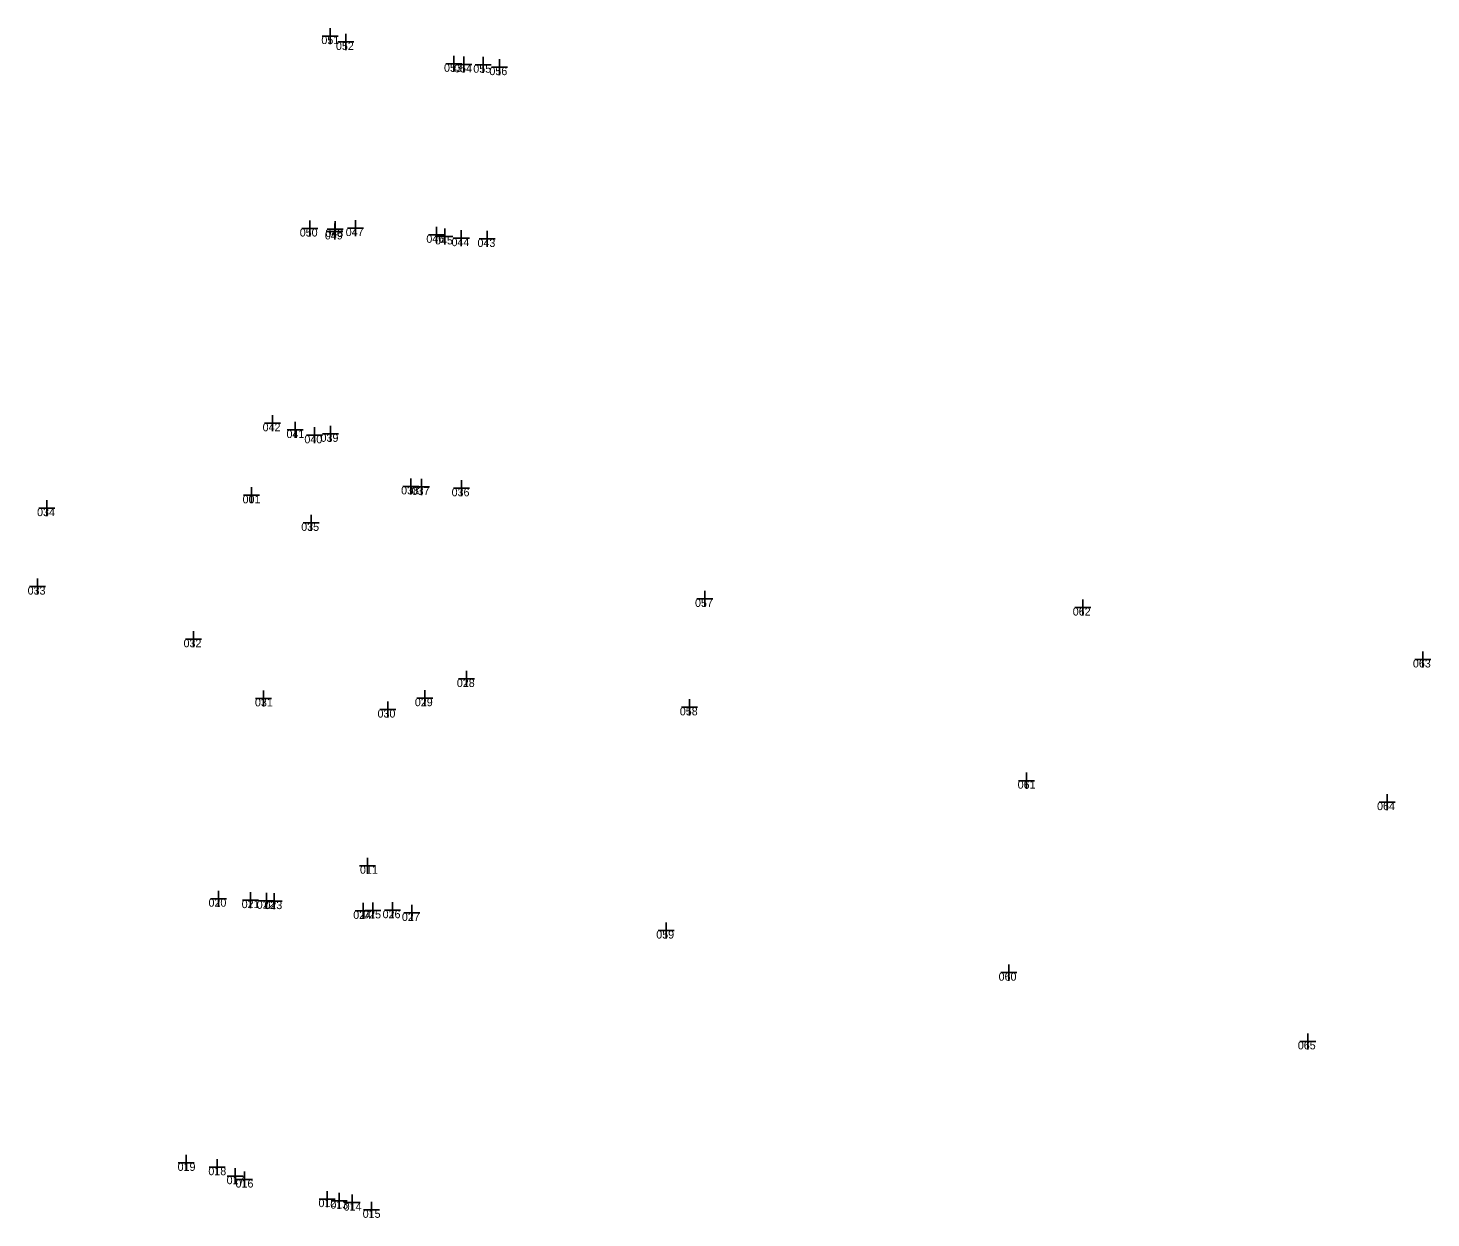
# Model space of a CAD drawing. Extents: x -706631 to -706106, y -1036183 to -1035074.
# Drawn here: x -706630.8 to -706543.1, y -1035148.6 to -1035074.3 of the extents above; entities that cross this region are included whole.
import ezdxf

# ---------------------------------------------------------------- set-up
doc = ezdxf.new("R2010")
doc.units = 0
doc.layers.add('čísla bodu', color=7, linetype='Continuous')

msp = doc.modelspace()

# ---------------------------------------------------------------- linework, layer by layer
at = {"layer": 'čísla bodu'}
for p, q in [((-706611.9, -1035075.32), (-706611.9, -1035074.32)), ((-706612.4, -1035074.82), (-706611.4, -1035074.82)), ((-706611.9, -1035074.82), (-706611.9, -1035074.82)), ((-706611.42, -1035075.19), (-706610.42, -1035075.19)), ((-706610.92, -1035075.69), (-706610.92, -1035074.69)), ((-706610.92, -1035075.19), (-706610.92, -1035075.19)), ((-706604.17, -1035077.05), (-706604.17, -1035076.05)), ((-706603.54, -1035077.09), (-706603.54, -1035076.09)), ((-706602.34, -1035077.11), (-706602.34, -1035076.11)), ((-706604.67, -1035076.55), (-706603.67, -1035076.55)), ((-706604.17, -1035076.55), (-706604.17, -1035076.55)), ((-706604.04, -1035076.59), (-706603.04, -1035076.59)), ((-706603.54, -1035076.59), (-706603.54, -1035076.59)), ((-706602.84, -1035076.61), (-706601.84, -1035076.61)), ((-706602.34, -1035076.61), (-706602.34, -1035076.61)), ((-706601.82, -1035076.76), (-706600.82, -1035076.76)), ((-706601.32, -1035077.26), (-706601.32, -1035076.26)), ((-706601.32, -1035076.76), (-706601.32, -1035076.76)), ((-706613.16, -1035087.34), (-706613.16, -1035086.34)), ((-706611.61, -1035087.52), (-706611.61, -1035086.52)), ((-706611.58, -1035087.37), (-706611.58, -1035086.37)), ((-706610.31, -1035087.31), (-706610.31, -1035086.31)), ((-706613.66, -1035086.84), (-706612.66, -1035086.84)), ((-706613.16, -1035086.84), (-706613.16, -1035086.84)), ((-706612.11, -1035087.02), (-706611.11, -1035087.02)), ((-706612.08, -1035086.87), (-706611.08, -1035086.87)), ((-706611.61, -1035087.02), (-706611.61, -1035087.02)), ((-706611.58, -1035086.87), (-706611.58, -1035086.87)), ((-706610.81, -1035086.81), (-706609.81, -1035086.81)), ((-706610.31, -1035086.81), (-706610.31, -1035086.81)), ((-706605.76, -1035087.23), (-706604.76, -1035087.23)), ((-706605.26, -1035087.73), (-706605.26, -1035086.73)), ((-706605.26, -1035087.23), (-706605.26, -1035087.23)), ((-706605.23, -1035087.33), (-706604.23, -1035087.33)), ((-706604.73, -1035087.83), (-706604.73, -1035086.83)), ((-706604.73, -1035087.33), (-706604.73, -1035087.33)), ((-706604.2, -1035087.44), (-706603.2, -1035087.44)), ((-706603.7, -1035087.94), (-706603.7, -1035086.94)), ((-706603.7, -1035087.44), (-706603.7, -1035087.44)), ((-706602.58, -1035087.49), (-706601.58, -1035087.49)), ((-706602.08, -1035087.99), (-706602.08, -1035086.99)), ((-706602.08, -1035087.49), (-706602.08, -1035087.49)), ((-706615.5, -1035099.5), (-706615.5, -1035098.5)), ((-706614.08, -1035099.92), (-706614.08, -1035098.92)), ((-706616, -1035099), (-706615, -1035099)), ((-706615.5, -1035099), (-706615.5, -1035099)), ((-706614.58, -1035099.42), (-706613.58, -1035099.42)), ((-706614.08, -1035099.42), (-706614.08, -1035099.42)), ((-706613.37, -1035099.75), (-706612.37, -1035099.75)), ((-706612.87, -1035100.25), (-706612.87, -1035099.25)), ((-706612.87, -1035099.75), (-706612.87, -1035099.75)), ((-706612.38, -1035099.66), (-706611.38, -1035099.66)), ((-706611.88, -1035100.16), (-706611.88, -1035099.16)), ((-706611.88, -1035099.66), (-706611.88, -1035099.66)), ((-706606.85, -1035103.44), (-706606.85, -1035102.44)), ((-706616.8, -1035104), (-706616.8, -1035103)), ((-706607.35, -1035102.94), (-706606.35, -1035102.94)), ((-706606.85, -1035102.94), (-706606.85, -1035102.94)), ((-706606.69, -1035102.98), (-706605.69, -1035102.98)), ((-706606.19, -1035103.48), (-706606.19, -1035102.48)), ((-706606.19, -1035102.98), (-706606.19, -1035102.98)), ((-706604.18, -1035103.06), (-706603.18, -1035103.06)), ((-706603.68, -1035103.56), (-706603.68, -1035102.56)), ((-706603.68, -1035103.06), (-706603.68, -1035103.06)), ((-706629.59, -1035104.8), (-706629.59, -1035103.8)), ((-706617.3, -1035103.5), (-706616.3, -1035103.5)), ((-706616.8, -1035103.5), (-706616.8, -1035103.5)), ((-706630.09, -1035104.3), (-706629.09, -1035104.3)), ((-706629.59, -1035104.3), (-706629.59, -1035104.3)), ((-706613.09, -1035105.72), (-706613.09, -1035104.72)), ((-706613.59, -1035105.22), (-706612.59, -1035105.22)), ((-706613.09, -1035105.22), (-706613.09, -1035105.22)), ((-706630.68, -1035109.2), (-706629.68, -1035109.2)), ((-706630.18, -1035109.7), (-706630.18, -1035108.7)), ((-706630.18, -1035109.2), (-706630.18, -1035109.2)), ((-706588.49, -1035110.47), (-706588.49, -1035109.47)), ((-706588.99, -1035109.97), (-706587.99, -1035109.97)), ((-706588.49, -1035109.97), (-706588.49, -1035109.97)), ((-706564.88, -1035111.01), (-706564.88, -1035110.01)), ((-706565.38, -1035110.51), (-706564.38, -1035110.51)), ((-706564.88, -1035110.51), (-706564.88, -1035110.51)), ((-706620.44, -1035112.99), (-706620.44, -1035111.99)), ((-706620.94, -1035112.49), (-706619.94, -1035112.49)), ((-706620.44, -1035112.49), (-706620.44, -1035112.49)), ((-706544.13, -1035113.75), (-706543.13, -1035113.75)), ((-706543.63, -1035114.25), (-706543.63, -1035113.25)), ((-706543.63, -1035113.75), (-706543.63, -1035113.75)), ((-706603.37, -1035115.47), (-706603.37, -1035114.47)), ((-706603.87, -1035114.97), (-706602.87, -1035114.97)), ((-706603.37, -1035114.97), (-706603.37, -1035114.97)), ((-706616.55, -1035116.18), (-706615.55, -1035116.18)), ((-706616.05, -1035116.68), (-706616.05, -1035115.68)), ((-706616.05, -1035116.18), (-706616.05, -1035116.18)), ((-706608.3, -1035117.38), (-706608.3, -1035116.38)), ((-706606.49, -1035116.17), (-706605.49, -1035116.17)), ((-706605.99, -1035116.67), (-706605.99, -1035115.67)), ((-706605.99, -1035116.17), (-706605.99, -1035116.17)), ((-706589.44, -1035117.24), (-706589.44, -1035116.24)), ((-706608.8, -1035116.88), (-706607.8, -1035116.88)), ((-706608.3, -1035116.88), (-706608.3, -1035116.88)), ((-706589.94, -1035116.74), (-706588.94, -1035116.74)), ((-706589.44, -1035116.74), (-706589.44, -1035116.74)), ((-706568.39, -1035121.82), (-706568.39, -1035120.82)), ((-706568.89, -1035121.32), (-706567.89, -1035121.32)), ((-706568.39, -1035121.32), (-706568.39, -1035121.32)), ((-706545.87, -1035123.16), (-706545.87, -1035122.16)), ((-706546.37, -1035122.66), (-706545.37, -1035122.66)), ((-706545.87, -1035122.66), (-706545.87, -1035122.66)), ((-706610.06, -1035126.63), (-706609.06, -1035126.63)), ((-706609.56, -1035127.13), (-706609.56, -1035126.13)), ((-706609.56, -1035126.63), (-706609.56, -1035126.63)), ((-706619.36, -1035128.69), (-706618.36, -1035128.69)), ((-706618.86, -1035129.19), (-706618.86, -1035128.19)), ((-706618.86, -1035128.69), (-706618.86, -1035128.69)), ((-706616.88, -1035129.28), (-706616.88, -1035128.28)), ((-706615.87, -1035129.32), (-706615.87, -1035128.32)), ((-706615.39, -1035129.34), (-706615.39, -1035128.34)), ((-706617.38, -1035128.78), (-706616.38, -1035128.78)), ((-706616.88, -1035128.78), (-706616.88, -1035128.78)), ((-706616.37, -1035128.82), (-706615.37, -1035128.82)), ((-706615.89, -1035128.84), (-706614.89, -1035128.84)), ((-706615.87, -1035128.82), (-706615.87, -1035128.82)), ((-706615.39, -1035128.84), (-706615.39, -1035128.84)), ((-706610.34, -1035129.45), (-706609.34, -1035129.45)), ((-706609.84, -1035129.95), (-706609.84, -1035128.95)), ((-706609.84, -1035129.45), (-706609.84, -1035129.45)), ((-706609.72, -1035129.42), (-706608.72, -1035129.42)), ((-706609.22, -1035129.92), (-706609.22, -1035128.92)), ((-706609.22, -1035129.42), (-706609.22, -1035129.42)), ((-706608.49, -1035129.41), (-706607.49, -1035129.41)), ((-706607.99, -1035129.91), (-706607.99, -1035128.91)), ((-706607.99, -1035129.41), (-706607.99, -1035129.41)), ((-706607.3, -1035129.58), (-706606.3, -1035129.58)), ((-706606.8, -1035130.08), (-706606.8, -1035129.08)), ((-706606.8, -1035129.58), (-706606.8, -1035129.58)), ((-706590.91, -1035131.18), (-706590.91, -1035130.18)), ((-706591.41, -1035130.68), (-706590.41, -1035130.68)), ((-706590.91, -1035130.68), (-706590.91, -1035130.68)), ((-706569.49, -1035133.81), (-706569.49, -1035132.81)), ((-706569.99, -1035133.31), (-706568.99, -1035133.31)), ((-706569.49, -1035133.31), (-706569.49, -1035133.31)), ((-706550.82, -1035138.1), (-706550.82, -1035137.1)), ((-706551.32, -1035137.6), (-706550.32, -1035137.6)), ((-706550.82, -1035137.6), (-706550.82, -1035137.6)), ((-706621.38, -1035145.19), (-706620.38, -1035145.19)), ((-706620.88, -1035145.69), (-706620.88, -1035144.69)), ((-706620.88, -1035145.19), (-706620.88, -1035145.19)), ((-706618.96, -1035145.96), (-706618.96, -1035144.96)), ((-706619.46, -1035145.46), (-706618.46, -1035145.46)), ((-706618.96, -1035145.46), (-706618.96, -1035145.46)), ((-706618.32, -1035146.02), (-706617.32, -1035146.02)), ((-706617.82, -1035146.52), (-706617.82, -1035145.52)), ((-706617.82, -1035146.02), (-706617.82, -1035146.02)), ((-706617.75, -1035146.23), (-706616.75, -1035146.23)), ((-706617.25, -1035146.73), (-706617.25, -1035145.73)), ((-706617.25, -1035146.23), (-706617.25, -1035146.23)), ((-706612.08, -1035147.95), (-706612.08, -1035146.95)), ((-706611.34, -1035148.05), (-706611.34, -1035147.05)), ((-706612.58, -1035147.45), (-706611.58, -1035147.45)), ((-706612.08, -1035147.45), (-706612.08, -1035147.45)), ((-706611.84, -1035147.55), (-706610.84, -1035147.55)), ((-706611.34, -1035147.55), (-706611.34, -1035147.55)), ((-706611.01, -1035147.67), (-706610.01, -1035147.67)), ((-706610.51, -1035148.17), (-706610.51, -1035147.17)), ((-706610.51, -1035147.67), (-706610.51, -1035147.67)), ((-706609.32, -1035148.62), (-706609.32, -1035147.62)), ((-706609.82, -1035148.12), (-706608.82, -1035148.12)), ((-706609.32, -1035148.12), (-706609.32, -1035148.12))]:
    msp.add_line(p, q, dxfattribs=at)

# ---------------------------------------------------------------- texts
for s, p in [('051', (-706612.442, -1035075.32)), ('052', (-706611.532, -1035075.69)), ('053', (-706604.782, -1035077.05)), ('054', (-706604.152, -1035077.09)), ('055', (-706602.952, -1035077.11)), ('056', (-706601.946, -1035077.26)), ('050', (-706613.794, -1035087.34)), ('049', (-706612.224, -1035087.52)), ('048', (-706612.192, -1035087.37)), ('047', (-706610.922, -1035087.31)), ('046', (-706605.886, -1035087.73)), ('045', (-706605.342, -1035087.83)), ('044', (-706604.312, -1035087.94)), ('043', (-706602.692, -1035087.99)), ('042', (-706616.112, -1035099.5)), ('041', (-706614.622, -1035099.92)), ('040', (-706613.504, -1035100.25)), ('039', (-706612.494, -1035100.16)), ('038', (-706607.462, -1035103.44)), ('037', (-706606.802, -1035103.48)), ('036', (-706604.306, -1035103.56)), ('001', (-706617.364, -1035104)), ('034', (-706630.202, -1035104.8)), ('035', (-706613.702, -1035105.72)), ('033', (-706630.792, -1035109.7)), ('057', (-706589.102, -1035110.47)), ('062', (-706565.506, -1035111.01)), ('032', (-706621.052, -1035112.99)), ('063', (-706544.256, -1035114.25)), ('028', (-706603.982, -1035115.47)), ('031', (-706616.592, -1035116.68)), ('029', (-706606.604, -1035116.67)), ('030', (-706608.934, -1035117.38)), ('058', (-706590.052, -1035117.24)), ('061', (-706568.946, -1035121.82)), ('064', (-706546.496, -1035123.16)), ('011', (-706610.032, -1035127.13)), ('020', (-706619.494, -1035129.19)), ('021', (-706617.422, -1035129.28)), ('022', (-706616.482, -1035129.32)), ('023', (-706616.002, -1035129.34)), ('024', (-706610.452, -1035129.95)), ('025', (-706609.832, -1035129.92)), ('026', (-706608.616, -1035129.91)), ('027', (-706607.412, -1035130.08)), ('059', (-706591.524, -1035131.18)), ('060', (-706570.137, -1035133.81)), ('065', (-706551.446, -1035138.1)), ('019', (-706621.423, -1035145.69)), ('018', (-706619.501, -1035145.96)), ('017', (-706618.361, -1035146.52)), ('016', (-706617.805, -1035146.73)), ('012', (-706612.621, -1035147.95)), ('013', (-706611.881, -1035148.05)), ('014', (-706611.051, -1035148.17)), ('015', (-706609.861, -1035148.62))]:
    msp.add_text(s, height=0.5, dxfattribs=at).set_placement(p)

doc.saveas('drawing.dxf')
